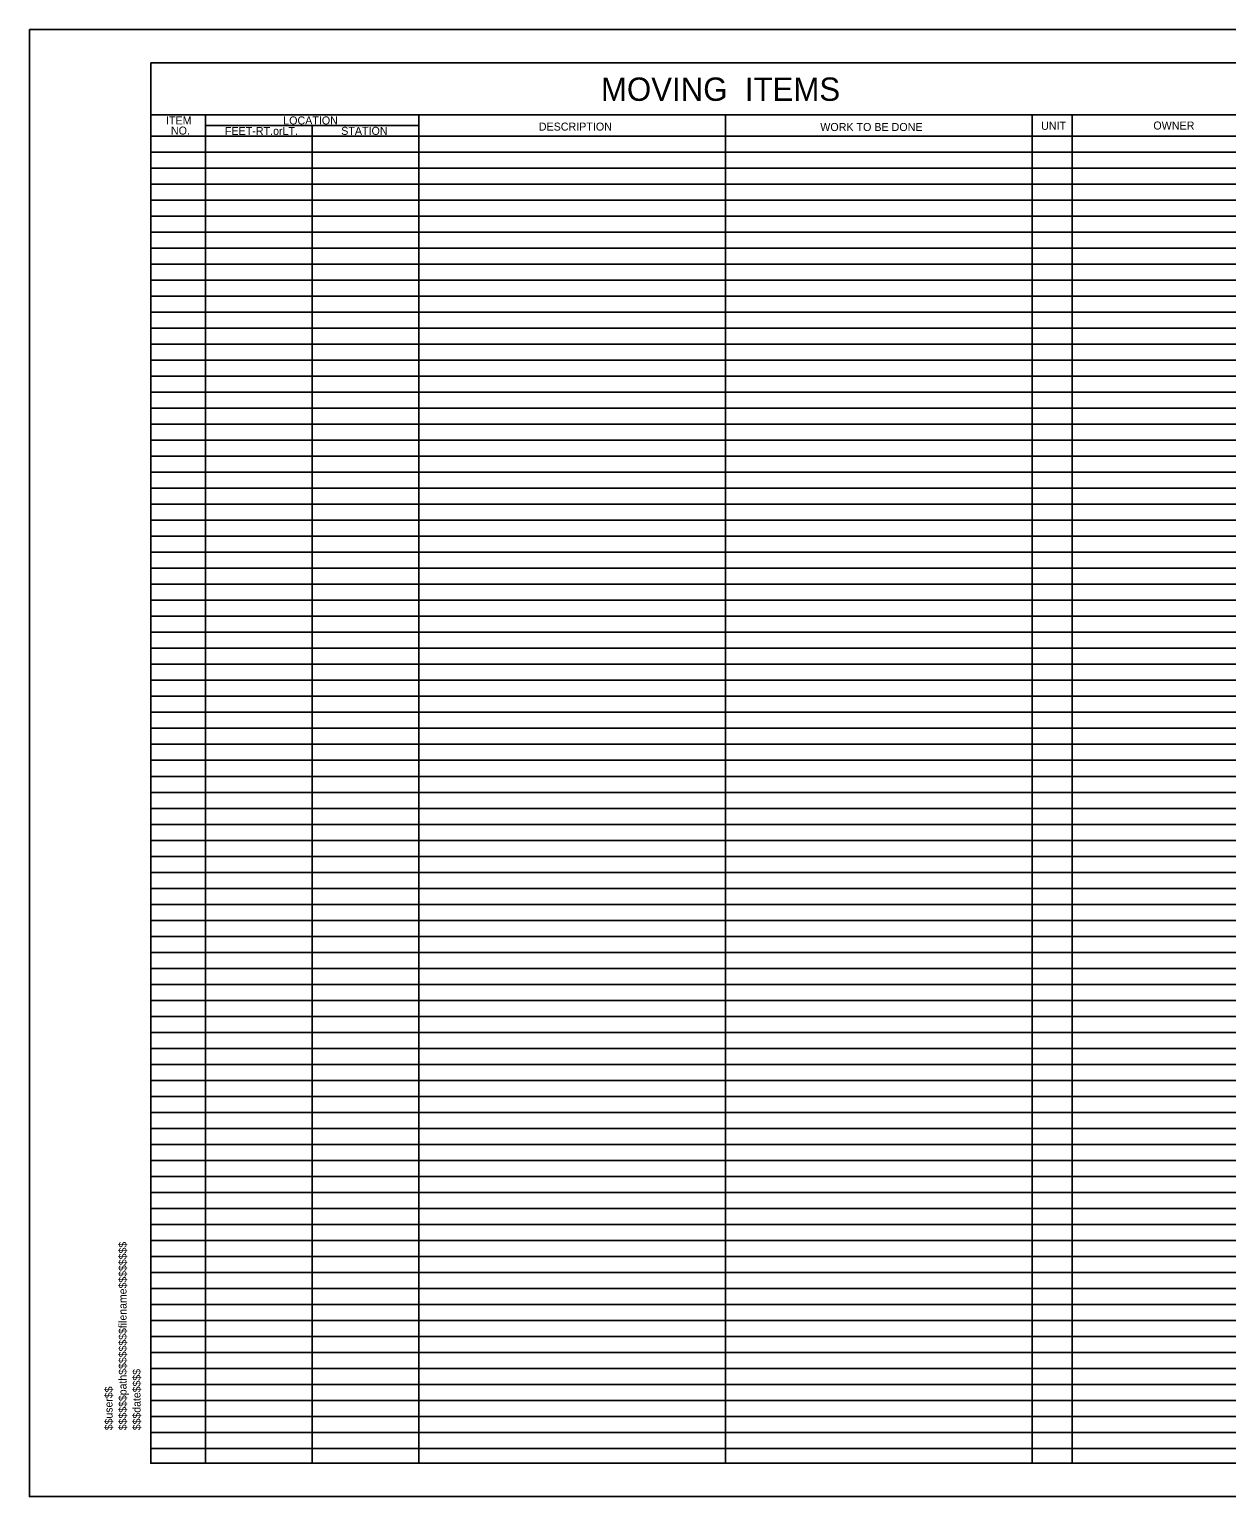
# Model space of a CAD drawing. Extents: x -796 to 2793, y -4650 to 4425.
# Drawn here: x 987 to 1884, y -2375 to -1275 of the extents above; entities that cross this region are included whole.
import ezdxf

# ---------------------------------------------------------------- set-up
doc = ezdxf.new("R2010")
doc.units = 0
for name, color, linetype in [('RD_HC_CL', 7, 'Continuous'), ('RD_HC_Data', 7, 'Continuous'), ('RD_HC_Data_Tic', 7, 'Continuous'), ('RD_TX_Misc1', 7, 'Continuous')]:
    doc.layers.add(name, color=color, linetype=linetype)

msp = doc.modelspace()

# ---------------------------------------------------------------- linework, layer by layer
at = {"layer": 'RD_HC_CL'}
msp.add_lwpolyline([(986.5, -1275), (2782.5, -1275), (2782.5, -2375), (986.5, -2375)], close=True, dxfattribs=at)
at = {"layer": 'RD_HC_Data'}
for p, q in [((2760, -1275), (1000, -1275)), ((1000, -1275), (2760, -1275)), ((2752.5, -1339), (1077.5, -1339)), ((1118.7, -1339), (1118.7, -2350)), ((1278.7, -1339), (1278.7, -2350)), ((1508.7, -1339.2), (1508.7, -2350)), ((1738.7, -1339), (1738.7, -2350)), ((1768.7, -1339), (1768.7, -2350)), ((1278.7, -1347), (1118.7, -1347)), ((1198.7, -1347), (1198.7, -2350)), ((2752.5, -1355), (1077.5, -1355)), ((2752.5, -1367), (1077.5, -1367)), ((2752.5, -1379), (1077.5, -1379)), ((2752.5, -1391), (1077.5, -1391)), ((2752.5, -1403), (1077.5, -1403)), ((2752.5, -1415), (1077.5, -1415)), ((2752.5, -1427), (1077.5, -1427)), ((2752.5, -1439), (1077.5, -1439)), ((2752.5, -1451), (1077.5, -1451)), ((2752.5, -1463), (1077.5, -1463)), ((2752.5, -1475), (1077.5, -1475)), ((2752.5, -1487), (1077.5, -1487)), ((2752.5, -1499), (1077.5, -1499)), ((2752.5, -1511), (1077.5, -1511)), ((2752.5, -1523), (1077.5, -1523)), ((2752.5, -1535), (1077.5, -1535)), ((2752.5, -1547), (1077.5, -1547)), ((2752.5, -1559), (1077.5, -1559)), ((2752.5, -1571), (1077.5, -1571)), ((2752.5, -1583), (1077.5, -1583)), ((2752.5, -1595), (1077.5, -1595)), ((2752.5, -1607), (1077.5, -1607)), ((2752.5, -1619), (1077.5, -1619)), ((2752.5, -1631), (1077.5, -1631)), ((2752.5, -1643), (1077.5, -1643)), ((2752.5, -1655), (1077.5, -1655)), ((2752.5, -1667), (1077.5, -1667)), ((2752.5, -1679), (1077.5, -1679)), ((2752.5, -1691), (1077.5, -1691)), ((2752.5, -1703), (1077.5, -1703)), ((2752.5, -1715), (1077.5, -1715)), ((2752.5, -1727), (1077.5, -1727)), ((2752.5, -1739), (1077.5, -1739)), ((2752.5, -1751), (1077.5, -1751)), ((2752.5, -1763), (1077.5, -1763)), ((2752.5, -1775), (1077.5, -1775)), ((2752.5, -1787), (1077.5, -1787)), ((2752.5, -1799), (1077.5, -1799)), ((2752.5, -1811), (1077.5, -1811)), ((2752.5, -1823), (1077.5, -1823)), ((2752.5, -1835), (1077.5, -1835)), ((2752.5, -1847), (1077.5, -1847)), ((2752.5, -1859), (1077.5, -1859)), ((2752.5, -1871), (1077.5, -1871)), ((2752.5, -1883), (1077.5, -1883)), ((2752.5, -1895), (1077.5, -1895)), ((2752.5, -1907), (1077.5, -1907)), ((2752.5, -1919), (1077.5, -1919)), ((2752.5, -1931), (1077.5, -1931)), ((2752.5, -1943), (1077.5, -1943)), ((2752.5, -1955), (1077.5, -1955)), ((2752.5, -1967), (1077.5, -1967)), ((2752.5, -1979), (1077.5, -1979)), ((2752.5, -1991), (1077.5, -1991)), ((2752.5, -2003), (1077.5, -2003)), ((2752.5, -2015), (1077.5, -2015)), ((2752.5, -2027), (1077.5, -2027)), ((2752.5, -2039), (1077.5, -2039)), ((2752.5, -2051), (1077.5, -2051)), ((2752.5, -2063), (1077.5, -2063)), ((2752.5, -2075), (1077.5, -2075)), ((2752.5, -2087), (1077.5, -2087)), ((2752.5, -2099), (1077.5, -2099)), ((2752.5, -2111), (1077.5, -2111)), ((2752.5, -2123), (1077.5, -2123)), ((2752.5, -2135), (1077.5, -2135)), ((2752.5, -2147), (1077.5, -2147)), ((2752.5, -2159), (1077.5, -2159)), ((2752.5, -2171), (1077.5, -2171)), ((2752.5, -2183), (1077.5, -2183)), ((2752.5, -2195), (1077.5, -2195)), ((2752.5, -2207), (1077.5, -2207)), ((2752.5, -2219), (1077.5, -2219)), ((2752.5, -2231), (1077.5, -2231)), ((2608.5, -2243), (1077.5, -2243)), ((2608.5, -2255), (1077.5, -2255)), ((2608.5, -2267), (1077.5, -2267)), ((2608.5, -2279), (1077.5, -2279)), ((2608.5, -2291), (1077.5, -2291)), ((2608.5, -2303), (1077.5, -2303)), ((2608.5, -2315), (1077.5, -2315)), ((2608.5, -2327), (1077.5, -2327)), ((2608.5, -2339), (1077.5, -2339)), ((2760, -2375), (1000, -2375)), ((1000, -2375), (2760, -2375))]:
    msp.add_line(p, q, dxfattribs=at)
msp.add_lwpolyline([(1077.5, -1300), (2752.5, -1300), (2752.5, -2350), (1077.5, -2350)], close=True, dxfattribs=at)

# ---------------------------------------------------------------- texts
at = {"layer": 'RD_HC_Data_Tic'}
for s, height, p in [('MOVING  ITEMS', 17.5, (1415.2, -1328.6)), ('ITEM', 6, (1089, -1346.3)), ('LOCATION', 6, (1176.9, -1346.3)), ('NO.', 6, (1092.7, -1353.9)), ('FEET-RT.orLT.', 6, (1133.2, -1354.2)), ('STATION', 6, (1220.4, -1354.1)), ('DESCRIPTION', 6, (1368.6, -1350.9)), ('WORK TO BE DONE', 6, (1579.7, -1351.2)), ('UNIT', 6, (1745.3, -1350.3)), ('OWNER', 6, (1829.5, -1350.1))]:
    msp.add_text(s, height=height, dxfattribs=at).set_placement(p)
at = {"layer": 'RD_TX_Misc1'}
for s, p in [('$$$$$$path$$$$$$$$filename$$$$$$$$', (1059.4, -2325.2)), ('$$$date$$$$', (1069.9, -2325.2)), ('$$user$$', (1048.9, -2325.2))]:
    msp.add_text(s, height=5.88, rotation=90, dxfattribs=at).set_placement(p)

doc.saveas('drawing.dxf')
